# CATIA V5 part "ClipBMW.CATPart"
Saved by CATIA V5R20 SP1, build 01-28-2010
Part number: ClipBMW
Bounding box of the stored display mesh (mm): x -8.997 to 8.997, y -8.997 to 8.997, z 0 to 22.1
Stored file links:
  C:\Users\quent\Documents\ClipBMW.CATPart
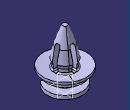
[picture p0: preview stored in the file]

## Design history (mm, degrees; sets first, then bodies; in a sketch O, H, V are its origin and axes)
Body1 (main body)
  Sketch1 on yz-plane, origin (0, 0, 0), H (0, 1, 0), V (0, 0, 1)
    axis line L1 (0, 83.2366) -> (0, -39.2961)
    point P1 (0, 83.2366)
    line L2 (0, 0) -> (7.25, 0)
    line L3 (7.25, 0) -> (7.25, 1.5)
    line L4 (7.25, 1.5) -> (3, 1.5)
    line L5 (3, 1.5) -> (3, 4.5)
    line L6 (3, 4.5) -> (7.45, 4.5)
    line L7 (7.45, 4.5) -> (7.45, 5.5)
    line L8 (7.45, 5.5) -> (5.2277, 5.5)
    line L9 (5.2277, 5.5) -> (5.2277, 6.5)
    line L10 (5.2277, 6.5) -> (9, 6.5)
    line L11 (9, 6.5) -> (9, 7.5)
    line L12 (9, 7.5) -> (4, 6.9)
    point P13 (4, 6.9)
    line L13 (4, 6.9) -> (4, 8.7015)
    line L14 (4, 8.7015) -> (4.5, 10.1)
    point P15 (4.5, 10.1)
    point P16 (1, 22.1)
    line L15 (1, 22.1) -> (0, 22.1)
    point P17 (0, 22.1)
    line L16 (1, 22.1) -> (3.5, 15.1)
    point P18 (3.5, 15.1)
    line L17 (3.5, 15.1) -> (4.5, 10.1)
    point P19 (4.5, 10.1)
    distance L4 L2 = 1.5
    "Radius" L3 L1 = 7.25
    "Radius" L5 L1 = 3
    "Radius" L7 L1 = 7.45
    "Radius" L11 L1 = 9
    distance L6 L4 = 3
    distance L8 L6 = 1
    length L11 = 1
    distance L10 L8 = 1
    distance P13 L10 = 0.4
    "Radius" L13 L1 = 4
    distance L15 P13 = 15.2
    "Radius" P15 L1 = 4.5
    "Radius" P18 L1 = 3.5
    "Radius" P16 L1 = 1
    distance P18 L15 = 7
    distance L15 P15 = 12
    coincidence: P1 V, L1 V, P17 L1, P19 L14, P15 P19
    horizontal: L2 H, L4 H, L6 H, L8 H, L10 H, L15 H
    vertical: L3 V, L5 V, L7 V, L9 V, L11 V, L13 V
  Shaft1: profile Sketch1, axis Sketch1.L1, angle 360
  Sketch2 on zx-plane, origin (0, 0, 0), H (-1, 0, 0), V (0, 0, 1)
    line L1 (-1, 6.9) -> (-1, 15.6709)
    line L2 (1, 15.6709) -> (1, 6.9)
    line L3 (1, 6.9) -> (-1, 6.9)
    arc A1 centre (0, 15.6709) radius 1 from (0, 16.6709) to (1, 15.6709) cw
    point P3 (0, 16.6709)
    reference projected line E1 (4, 6.9) -> (-4, 6.9) from edge [face of Shaft1 from Sketch1.L13 | face of Shaft1 from Sketch1.L12]
    arc A2 centre (0, 15.6709) radius 1 from (0, 16.6709) to (-1, 15.6709) ccw
    point P6 (0, 16.6709)
    distance L1 L2 = 2
    radius A2 = 1
    distance P3 L3 = 9.7709
    vertical: L1 V, L2 V
    horizontal: L3 H
    tangency: A1 L2, A2 L1, A2 A1
    symmetry: L2 L1 V
    coincidence: L3 E1, P6 P3, P3 V
  Pocket1: profile Sketch2, direction (0, -1, 0), length 4.5, mirrored extent
  CircPattern1: of Pocket1, instances 2, angular step 90, axis from xy-plane
  Sketch3 on face of Shaft1 from Sketch1.L2, origin (0, 0, 0), H (1, 0, 0), V (0, -1, 0)
    arc A1 centre (0, 0) radius 3 from (2.625, 1.4524) to (0, 3) ccw
    point P1 (0, 3)
    line L1 (3.75, 1.7428) -> (3.75, 4.3243)
    point P2 (3.75, 6.2048)
    arc A2 centre (3.15, 1.7428) radius 0.6 from (2.625, 1.4524) to (3.75, 1.7428) ccw
    point P3 (2.625, 1.4524)
    point P4 (3.75, 1.7428)
    projected circle E1 centre (0, 0) radius 7.25 from edge [face of Shaft1 from Sketch1.L3 | face of Shaft1 from Sketch1.L2]
    projected arc E2 centre (0, 0) radius 7.25 from (5.3091, 4.9372) to (-5.3091, 4.9372) ccw from edge [face of Shaft1 from Sketch1.L3 | face of Shaft1 from Sketch1.L2]
    arc A3 centre (4.65, 4.3243) radius 0.9 from (5.3091, 4.9372) to (3.75, 4.3243) ccw
    point P6 (5.3091, 4.9372)
    point P7 (3.75, 4.3243)
    point P9 (-3.75, 4.3243)
    point P10 (-5.3091, 4.9372)
    arc A4 centre (-4.65, 4.3243) radius 0.9 from (-5.3091, 4.9372) to (-3.75, 4.3243) cw
    point P12 (-3.75, 1.7428)
    line L2 (-3.75, 1.7428) -> (-3.75, 4.3243)
    point P13 (-2.625, 1.4524)
    arc A5 centre (-3.15, 1.7428) radius 0.6 from (-2.625, 1.4524) to (-3.75, 1.7428) cw
    point P15 (0, 3)
    arc A6 centre (0, 0) radius 3 from (-2.625, 1.4524) to (0, 3) cw
    radius A1 = 3
    radius A2 = 0.6
    radius A3 = 0.9
    distance L1 V = 3.75
    coincidence: P1 V, P2 E1, L1 P2, P1 P15
    vertical: L1 V
    tangency: A2 A1, A2 L1, A3 L1, A3 E1
    symmetry: P7 P9 V, P6 P10 V, A3 A4 V, P4 P12 V, L1 L2 V, P3 P13 V, A2 A5 V, P1 P15 V, A1 A6 V
  Pocket2: profile Sketch3, direction (0, 0, 1), through (limit type 6)
  Fillet1: radius 0.5, on edge [face of Shaft1 from Sketch1.L13 | face of Shaft1 from Sketch1.L12] (x4); edge [face of CircPattern1 | face of Pocket1 from Sketch2.L1] (x2); edge [face of CircPattern1 | face of CircPattern1] (x4); edge [face of Pocket1 from Sketch2.L2 | face of CircPattern1] (x2); edge [face of Shaft1 from Sketch1.L10 | face of Shaft1 from Sketch1.L9]; edge [face of Shaft1 from Sketch1.L9 | face of Shaft1 from Sketch1.L8]; edge [face of Shaft1 from Sketch1.L6 | face of Shaft1]; edge [face of Shaft1 | face of Shaft1 from Sketch1.L4]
